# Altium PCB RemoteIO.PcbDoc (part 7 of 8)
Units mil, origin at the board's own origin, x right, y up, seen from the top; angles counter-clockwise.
Board outline 7874.02 x 2362.2 mil, 6 copper layers (Top Layer, GND1, Layer 2, PWR, GND2, Bottom Layer), stack 60.956 mil thick; 655 components, 447 nets, 2607 pads, 1444 vias.
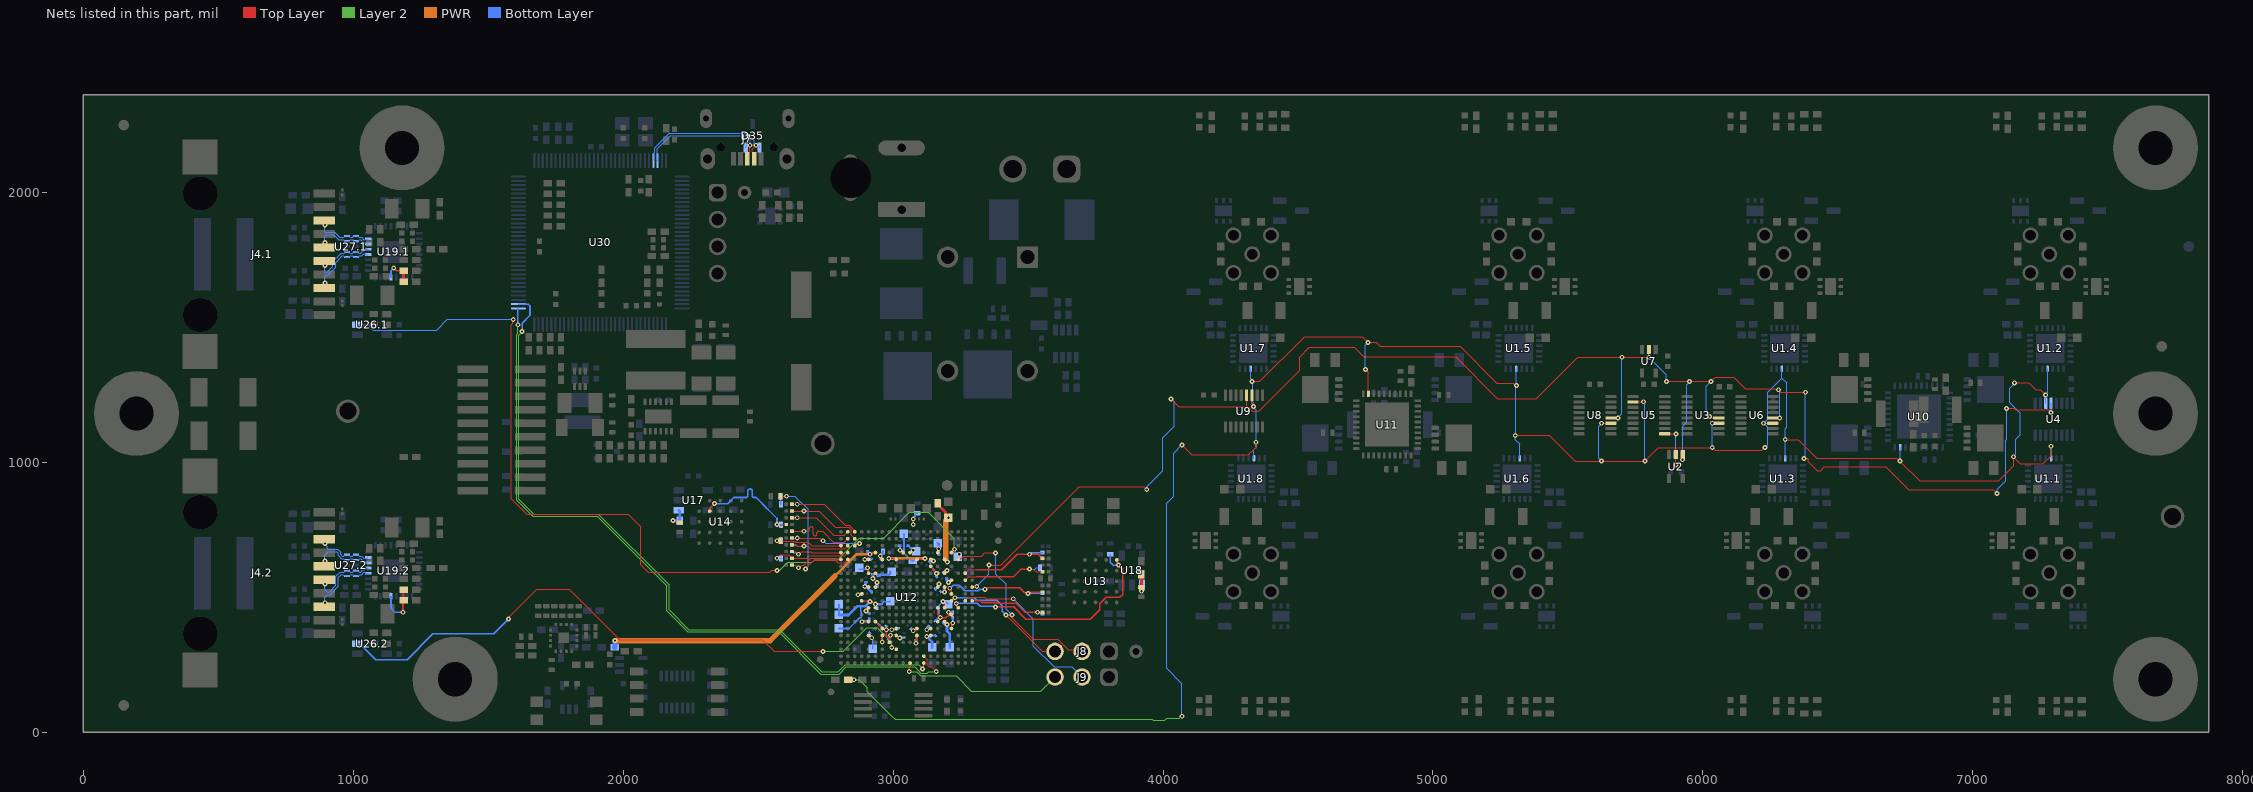
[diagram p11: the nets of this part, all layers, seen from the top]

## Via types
v1: diameter 18, hole 8, Top Layer to Bottom Layer, tented both sides, 1277 vias
v2: diameter 19.68, hole 7.87, Top Layer to Bottom Layer, tented both sides, 133 vias
v3: diameter 19.68, hole 7.87, Top Layer to Bottom Layer, 34 vias

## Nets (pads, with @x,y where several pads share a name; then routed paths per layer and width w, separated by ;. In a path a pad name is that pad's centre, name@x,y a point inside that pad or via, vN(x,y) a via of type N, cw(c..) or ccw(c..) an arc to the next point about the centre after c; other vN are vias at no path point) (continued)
OSPI0_D5: R49.1 R58.1 U12.K1 | length 299.4
  Top Layer w4: v1(3535,445) R58.1@3553.98,445
  Top Layer w6: U12.K1@3293.11,487.2 3322.8,487.2 3329,481 3386.63,481 3388.63,479 3455,479 3489,445 v1(3535,445)
  Bottom Layer w6: v1(3535,445) 3537.3,442.7 3549.89,442.7 3552.59,440 R49.1@3553.98,440
OSPI0_D6: R50.1 R59.1 U12.P2 | length 374.2
  Top Layer w4: U12.P2@3267.52,589.57 3282.28,604.33 3286.42,604.33 3287.98,602.77 3310,602.77
  Top Layer w5: R59.1@3553.19,645 R59.1@3553.98,645
  Top Layer w6: 3310,602.77 3402.77,602.77 3460,660 v1(3505,660) 3538.19,660 R59.1@3553.19,645
  Bottom Layer w5: v1(3505,660) 3508.52,660 3513.52,665
  Bottom Layer w6: 3513.52,665 R50.1@3553.98,665
OSPI0_D7: R51.1 R60.1 U12.L4 | length 454.5
  Top Layer w5: v1(3340,530) 3342.93,530 3349.43,536.5 3468.5,536.5 3488.33,516.67 3498.33,516.67 v1(3500,515) 3503.52,515 3508.52,520 R60.1@3553.98,520 R60.1@3558.34,520
  Top Layer w6: v1(3210.21,534.14) 3210.21,530.89 3214.85,526.26 3214.85,514.28 U12.L4@3216.34,512.8
  Bottom Layer w5: v1(3210.21,534.14) 3211.83,534.14 3222.69,545 3245,545 3265,525 3315.22,525 3320.22,530 v1(3340,530) ; v1(3500,515) R51.1@3553.98,515
OSPI0_DQS: R52.1 R61.2 U12.N2 | length 349.7
  Top Layer w4: U12.N2@3267.52,563.98 3279.91,576.37 3310,576.37 ; v1(3505,605) 3520,605 3530,595 R52.1@3553.98,595
  Top Layer w6: 3310,576.37 3446.37,576.37 3475,605 v1(3505,605)
  Bottom Layer w4: v1(3505,605) 3525,605 3530,610 R61.2@3545,610
OSPI0_ECC_FAIL: R42.1 U12.J3 U13.A5 | length 910.5
  Top Layer w5: v1(3380,465) 3446.31,465 3491.31,420 3730,420 3765,455 3765,475.83 3789.17,500 3840,500 3850,510 3850,605 v1(3835,620) 3830.42,624.58 3830.42,637.06 U13.A5@3828.74,638.74
  Top Layer w6: v1(3234,477.75) 3236.29,475.46 3236.29,469.36 3241.93,463.72 U12.J3@3241.93,461.61
  Bottom Layer w5: v1(3234,477.75) 3312.25,477.75 3322.51,467.49 3377.51,467.49 v1(3380,465) ; R42.1@3805,660 3805,630 3815,620 v1(3835,620)
OSPI0_RST: R97.1 R98.1 U18.1 | length 83.7
  Top Layer w10: v1(3920,523.16) R98.1@3920,537.72 R97.1@3920,585
  Bottom Layer w10: v1@3920,525 3921.2,526.2 3921.2,544.67 U18.1@3922.4,545.87
OSPI1_C\S\: R64.1 R87.1 R88.1 U12.T19 | length 583.5
  Top Layer w4: R87.1@2582.72,875 v1(2605,875) ; v1(2675,605) 2675,607.66 2705.29,637.95 2785.41,637.95 2795,628.36 2820.09,628.36 U12.T19@2832.48,640.75
  Bottom Layer w4: R88.1@2582.72,875 v1(2605,875) 2636.21,875 2651.21,860 2685,826.21 2685,825 2685.77,824.23 2685.77,615.77 v1(2675,605)
  Bottom Layer w6: R88.1@2582.72,875 2583.86,873.86 2583.86,846.14 R64.1@2585,845
OSPI1_CLK: R84.2 R86.1 U14.B2 | length 431.1
  Top Layer w4: v1(2570,770) R86.1@2603.98,770
  Top Layer w6: U14.B2@2320.63,819.37 2320.63,829.89 v1(2338.26,847.52)
  Bottom Layer w4: v1(2570,770) R84.2@2585,770
  Bottom Layer w6: v1(2338.26,847.52) 2387.52,847.52 2410,870 2451.33,870 2454.33,870 ccw(c2454.33,878) 2462.33,878 2462.33,893.72 cw(c2470.33,893.72) 2478.33,893.72 2478.33,878 ccw(c2486.33,878) 2486.33,870 2492.66,870 2500.18,862.48 2530.5,832.16 2530.5,830.1 2534.6,826 2536.66,826 2570,792.66 v1(2570,770)
OSPI1_D0: R65.1 R75.1 U12.V19 | length 264
  Top Layer w4: R75.1@2626.02,695 2639.11,695 2644.11,690 v1(2670,690) 2685,690 2695.46,679.54 2820.09,679.54 U12.V19@2832.48,691.93
  Bottom Layer w4: R65.1@2626.02,695 2639.11,695 2644.11,690 v1(2670,690)
OSPI1_D1: R66.1 R76.1 U12.Y18 | length 296.2
  Top Layer w4: R76.1@2626.02,845 v1(2645,845) 2745,845 2822,768 2838.31,768 2853.1,753.21 2855.4,750.91 2855.4,750.34 2856.2,749.54 2856.2,744.98 U12.Y18@2858.07,743.11
  Bottom Layer w4: R66.1@2626.02,845 v1(2645,845)
OSPI1_D2: R67.1 R77.1 U12.W18 | length 329.8
  Top Layer w4: R77.1@2626.02,820 v1(2670,820) 2726.31,820 2786.31,760 2835,760 2845.6,749.4 2845.6,729.99 U12.W18@2858.07,717.52
  Bottom Layer w4: R67.1@2626.02,820 v1(2670,820)
OSPI1_D3: R68.1 R78.1 U12.Y19 | length 257.8
  Top Layer w4: R78.1@2626.02,795 v1(2645,795) 2715,795 2780,730 2819.37,730 U12.Y19@2832.48,743.11
  Bottom Layer w4: R68.1@2626.02,795 v1(2645,795)
OSPI1_D4: R69.1 R79.1 U12.W19 | length 322.2
  Top Layer w4: R79.1@2626.02,745 v1(2670,745) 2681,745 2683,745 ccw(c2683,752) 2690,752 2690,755 cw(c2697,755) 2704,755 2704,735 ccw(c2711,735) 2718,735 2718,738 cw(c2725,738) 2725,745 2738.69,745 2778.69,705 2819.96,705 U12.W19@2832.48,717.52
  Bottom Layer w4: R69.1@2626.02,745 v1(2670,745)
OSPI1_D5: R70.1 R80.1 U12.U20 | length 218.8
  Top Layer w4: R80.1@2626.02,670 2639.11,670 2649.11,660 v1(2650,660) 2651.21,660 2661.21,670 2695,670 2698.66,666.34 U12.U20@2806.89,666.34
  Bottom Layer w4: R70.1@2626.02,670 2630.32,665.7 2640.51,665.7 2646.21,660 v1(2650,660)
OSPI1_D6: R71.1 R81.1 U12.T20 | length 230.2
  Top Layer w4: R81.1@2626.02,620 2639.11,620 2649.11,610 v1(2650,610) 2651.21,610 2661.21,620 2670,620 2695.95,645.95 2789.8,645.95 2795,640.75 U12.T20@2806.89,640.75
  Bottom Layer w4: R71.1@2626.02,620 2639.11,620 2649.11,610 v1(2650,610)
OSPI1_D7: R72.1 R82.1 U12.V18 | length 296.5
  Top Layer w4: R82.1@2626.02,720 v1(2645,720) 2728.79,720 2738.79,710 v1(2740,710)
  Top Layer w5: U12.V18@2858.07,691.93 2860.45,691.93 2866.03,697.51 2872.51,697.51 v1(2875,700)
  Bottom Layer w4: R72.1@2626.02,720 v1(2645,720) ; v1(2740,710) 2741.21,710 2751.21,700 v1(2875,700)
OSPI1_DQS: R74.1 R83.2 U12.U19 | length 296.1
  Top Layer w4: v1(2570,645) 2582.3,657.3 2613.55,657.3 2620.94,649.91 2620.94,649.3 R74.1@2625.24,645 ; R74.1@2626.02,645 2680,645 2688.95,653.95 2820.09,653.95 U12.U19@2832.48,666.34
  Bottom Layer w4: v1(2570,645) R83.2@2585,645
OSPI1_ECC_FAIL: R63.1 R73.1 U12.V20 | length 257.1
  Top Layer w4: v1(2570,710) R73.1@2582.72,710 ; R73.1@2585,710 2587.5,707.5 2635.39,707.5 2637.89,705 2685,705 2698.07,691.93 U12.V20@2806.89,691.93
  Bottom Layer w4: v1(2570,710) R63.1@2585,710
OSPI1_RST: R95.1 R99.1 U17.1 | length 94.3
  Top Layer w4: v1(2185,785) 2192.28,777.72 R99.1@2210,777.72
  Bottom Layer w5: v1(2185,785) 2208.62,785 R95.1@2210,783.62
  Bottom Layer w10: U17.1@2205.87,822.6 2210,818.46 R95.1@2210,783.62
RD.1_N: J4.1.8 U19.1.4 U27.1.1 U27.1.10 | length 262.8
  Top Layer w4.32: J4.1.8@892.91,1646.65 892.91,1662.91 v1(895,1665)
  Bottom Layer w4.32: v1(895,1665) 895,1690.31 897.53,1692.84 904.97,1692.84 934.41,1722.28 934.41,1740.7 959.52,1765.81 965.63,1765.81 968.16,1763.28 968.16,1762.41 969.94,1760.63 U27.1.1@977.13,1760.63 984.31,1760.63 986.09,1762.41 986.09,1763.28 988.62,1765.81 998.51,1765.81 1001.04,1763.28 1001.04,1762.41 1002.81,1760.63 U27.1.10@1010,1760.63 1017.19,1760.63 1018.96,1762.41 1018.96,1763.28 1021.49,1765.81 1031.46,1765.81 1039.75,1774.1 1044.68,1774.1 1048.62,1770.16 U19.1.4@1055.51,1770.16
RD.1_P: J4.1.6 U19.1.5 U27.1.2 U27.1.9 | length 262.1
  Top Layer w4.32: J4.1.6@892.91,1746.65 895,1744.57 v1(895,1730)
  Bottom Layer w4.32: v1(895,1730) 895,1704.69 897.53,1702.16 901.11,1702.16 925.09,1726.14 925.09,1744.56 955.66,1775.13 965.63,1775.13 968.16,1777.66 968.16,1778.54 969.94,1780.32 U27.1.2@977.13,1780.32 984.31,1780.32 986.09,1778.54 986.09,1777.66 988.62,1775.13 998.51,1775.13 1001.04,1777.66 1001.04,1778.54 1002.81,1780.32 U27.1.9@1010,1780.32 1017.19,1780.32 1018.96,1778.54 1018.96,1777.66 1021.49,1775.13 1027.6,1775.13 1035.89,1783.42 1042.2,1783.42 1048.62,1789.84 U19.1.5@1055.51,1789.84
RD.2_N: J4.2.8 U19.2.4 U27.2.1 U27.2.10 | length 280.3
  Top Layer w4.32: J4.2.8@892.91,465.55 897.36,470 J4.2.8@920,470
  Bottom Layer w4.32: v1(895,480) 895,500.68 905,510.68 914.54,510.68 945,541.14 945,574.71 955,584.71 959.52,584.71 965.63,584.71 968.16,582.18 968.16,581.3 969.94,579.53 U27.2.1@977.13,579.53 984.31,579.53 986.09,581.3 986.09,582.18 988.62,584.71 998.51,584.71 1001.04,582.18 1001.04,581.3 1002.81,579.53 U27.2.10@1010,579.53 1017.19,579.53 1018.96,581.3 1018.96,582.18 1021.49,584.71 1031.46,584.71 1039.75,593 1044.68,593 1048.62,589.06 U19.2.4@1055.51,589.06
RD.2_P: J4.2.6 U19.2.5 U27.2.2 U27.2.9 | length 268.1
  Top Layer w4.32: J4.2.6@892.91,565.55 895,563.46 v1(895,550)
  Bottom Layer w4.32: v1(895,550) 895,530 905,520 910.68,520 935.68,545 935.68,578.57 951.14,594.03 955.66,594.03 965.63,594.03 968.16,596.56 968.16,597.44 969.94,599.21 U27.2.2@977.13,599.21 984.31,599.21 986.09,597.44 986.09,596.56 988.62,594.03 998.51,594.03 1001.04,596.56 1001.04,597.44 1002.81,599.21 U27.2.9@1010,599.21 1017.19,599.21 1018.96,597.44 1018.96,596.56 1021.49,594.03 1027.6,594.03 1035.89,602.32 1042.2,602.32 1048.62,608.74 U19.2.5@1055.51,608.74
RESET_PHY0: U12.U4 U26.1.2 | length 3294
  Top Layer w4: v1(1593,1530) 1591,1528 1591,1515 1586,1510 1586,865.31 1643.31,808 2018.12,808 2065,761.12 2065,620.51 2092.51,593 2543,593 2550,600 v1(2570,600)
  Top Layer w6: U12.U4@3216.34,666.34 3216.34,666.95 3227.5,678.11 v1(3227.5,678.72)
  Layer 2 w4: v1(2570,600) 2580,600 2610,630 2700,630 2710,640 2794.49,640 2874.49,720 2965,720 3060,815 3130,815 3227.5,717.5 v1(3227.5,678.72)
  Bottom Layer w4: U26.1.2@1015.87,1510 1055,1510 1074.59,1490.41 1308.67,1490.41 1348.27,1530 v1(1593,1530)
RESET_PHY1: U12.C12 U26.2.2 | length 2308.5
  Top Layer w4: v1(1575,420) 1574.16,420.84 1574.16,424.16 1680,530 1801.06,530 1826.06,505 1826.21,505 1987.21,344 2515.49,344 2559.49,300 v1(2740,300) ; v1(2995.01,314.28) 2998.8,314.28 3003.13,309.94 3009.74,309.94 U12.C12@3011.61,308.07
  Layer 2 w4: v1(2740,300) 2785,300 2815.34,300 2902.34,387 2942.49,387 2944.99,384.5 2946.01,384.5 2975.5,355.01 2975.5,353.99 2983.99,345.5 2985.01,345.5 2995.01,335.5 v1(2995.01,314.28)
  Bottom Layer w5: U26.2.2@1015.87,328.9 1023.74,328.9 1082.64,270 1200,270 1295,365 1520,365 v1(1575,420)
SCLK: R40.2 U1.1.22 U1.2.22 U1.3.22 U1.4.22 U1.5.22 U1.6.22 U1.7.22 U1.8.22 U3.11 U4.11 U5.2 U6.11 U8.11 U9.11 U10.9 U11.9 | length 8786.6
  Top Layer w4: R40.2@2833.62,195 v1(2855,195) ; v1(4070,1065) 4107,1028 4316.69,1028 4345,1056.31 v1(4345,1075) ; U9.11@4329.53,1249.06 4329.53,1216.79 4335.53,1210.79 v1(4335.53,1207) ; v1(4330,1300) 4358.79,1300 4524.79,1466 4739,1466 v1(4760,1445) 4790,1445 4804,1431 5100.31,1431 5237.31,1294 5297.79,1294 5306.79,1285 v1(5310,1285) ; v1(4750,1345) 4761.1,1333.9 U11.9@4761.1,1254.17 ; v1(5305,1100) 5431.31,1100 5526.31,1005 v1(5625,1005) v1(5785,1005) 5835,1055 v1(6035,1055) 6036.21,1055 6046.21,1045 6218.79,1045 6228.79,1055 v1(6230,1055) ; v1(5625,1145) 5625.47,1145.47 U8.11@5659.06,1145.47 ; U5.2@5740.94,1224.21 5741.34,1224.61 5779.61,1224.61 v1(5780,1225) ; v1(6035,1145) 6058.58,1145 U3.11@6059.06,1145.47 ; v1(6225,1145) 6225.24,1145.24 6258.82,1145.24 U6.11@6259.06,1145.47 ; v1(6305,1085) 6352.47,1085 6421.47,1016 6719,1016 v1(6730,1005) 6803,932 7095.79,932 7151.21,987.43 v1@7151.21,1018.79 ; v1(7151.21,1021.21) v1@7151.21,1018.79 ; v1@7160,1295 7207.37,1295 7232.37,1270 7250,1270 v1(7270,1250) ; v1(7290,1060) 7290,1025 7260,995 7175,995 v1@7151.21,1018.79
  Layer 2 w4: v1(2855,195) 2875,195 2905,165 2905,151.31 2992.31,64 3008.31,48 3960.79,48 3963.79,45 4006.21,45 4014.21,53 4060.66,53 4067.66,60 v1(4070,60)
  Bottom Layer w4: v1(4070,60) 4070,179.74 4013,236.74 4013,849.06 4039,875.06 4039,1034 v1(4070,1065) ; U1.7.22@4324.33,1346.91 4324.33,1309.46 4330,1303.79 v1(4330,1300) 4331.77,1298.23 4331.77,1224 4333.77,1222 4333.77,1205 4345,1193.77 v1(4345,1075) 4345,1055 4337.09,1047.09 U1.8.22@4337.09,1015.3 ; v1(4750,1345) 4750,1433.79 4760,1443.79 v1(4760,1445) ; U1.5.22@5308.58,1346.91 5309.29,1346.2 5309.29,1285.71 v1(5310,1285) 5307.5,1282.5 5307.5,1102.5 v1(5305,1100) 5305,1085 5321.34,1068.66 U1.6.22@5321.34,1015.3 ; v1(5625,1005) 5615,1015 5615,1135 v1(5625,1145) ; v1(5780,1225) 5780,1221.21 5785,1216.21 v1(5785,1005) ; v1(6035,1055) v1(6035,1145) ; v1(6230,1055) 6230,1056.21 6240,1066.21 6240,1130 v1(6225,1145) 6240,1160 6240,1260 6292.83,1312.83 ; U1.4.22@6292.83,1346.91 6292.83,1312.83 ; U1.3.22@6305.59,1015.3 6305.3,1015.59 6305.3,1084.7 v1(6305,1085) 6305,1125 6310,1130 6310,1295.67 6292.83,1312.83 ; v1(6730,1005) 6730.55,1005.55 6730.55,1055.28 U10.9@6731.1,1055.83 ; v1@7151.21,1021.54 7160,1030.33 7160,1086.21 7176,1102.21 7176,1182.69 7137,1221.69 7137,1275.79 7155,1293.79 v1(7155,1295) ; U4.11@7270.47,1219.06 7270.24,1219.29 7270.24,1249.76 v1(7270,1250) 7270,1253.79 7277.09,1260.87 U1.2.22@7277.09,1346.91 ; U1.1.22@7289.84,1015.3 7289.92,1015.37 7289.92,1059.92 v1(7290,1060)
SR_C\S\: U2.1 U3.12 U4.12 U6.12 U7.2 U8.12 U9.12 U12.M1 | length 6454.5
  Top Layer w4: U12.M1@3293.11,538.39 3294.42,539.69 3308.69,539.69 v1(3310,541) ; v1(3355,620) 3398.94,620 3688.94,910 3930,910 v1(3940,900) ; v1(4030,1235) 4059,1206 4309.84,1206 ; U9.12@4309.84,1249.06 4309.84,1206 ; U8.12@5659.06,1165.16 5659.13,1165.08 5684.92,1165.08 v1(5685,1165) ; U7.2@5800,1419.29 v1(5800,1390) v1(5700,1390) 5536.47,1390 5382.47,1236 5238.75,1236 5083.75,1391 4743.75,1391 4708.75,1426 4541.36,1426 4506,1390.64 4506,1341 4355,1190 4331.31,1190 4315.31,1206 4309.84,1206 ; v1(5865,1300) v1(5950,1300) v1(6030,1300) 6045,1315 6115,1315 6156.21,1273.79 6266.21,1273.79 6268.81,1271.19 6277.97,1271.19 v1(6280,1269.16) 6289.16,1260 v1(6380,1260) ; v1(5925,1010) 5925.59,1010.59 U2.1@5925.59,1029.29 ; v1(6025,1170) 6028.79,1170 6033.63,1165.16 U3.12@6059.06,1165.16 ; U6.12@6259.06,1165.16 6259.13,1165.08 6285,1165.08 v1(6285.08,1165) ; v1(6375,1015) 6388.53,1015 6390.88,1012.66 6390.88,1002.91 6423.79,970 6436.21,970 6450.21,984 6678.37,984 6763.37,899 7076,899 v1(7090,885) ; v1(7125,1200) 7153,1200 7157.79,1195.21 7282.31,1195.21 7290,1187.53 v1(7290,1185)
  Bottom Layer w4: v1(3310,541) 3355,586 v1(3355,620) ; v1(3940,900) 3941.61,901.61 3941.61,911.61 3999,969 3999,1091.63 4040.86,1133.49 4040.86,1224.14 v1(4030,1235) ; v1(5685,1165) 5700,1180 v1(5700,1390) ; v1(5800,1390) 5865,1325 v1(5865,1300) ; v1(5925,1010) 5925,1133.79 5940,1148.79 5940,1288.79 5950,1298.79 v1(5950,1300) ; v1(6025,1170) 6025,1172.34 6018.67,1178.67 6018.67,1189.27 6013,1194.95 6013,1283 v1(6030,1300) ; v1(6280,1269.16) 6280,1265.37 6285.08,1260.3 v1(6285.08,1165) ; v1(6375,1015) 6380,1020 v1(6380,1260) ; v1(7090,885) 7090,900 7122,932 7122,1082.15 7125,1085.15 v1(7125,1200) ; v1(7290,1185) 7290.16,1185.16 U4.12@7290.16,1219.06
SR_OUT: U2.2 U5.9 | length 195.7
  Top Layer w4: U5.9@5859.06,1106.1 5859.61,1105.55 5899.45,1105.55 v1(5900,1105) ; v1(5900,990) U2.2@5900,1029.29
  Bottom Layer w4: v1(5900,990) v1(5900,1105)
Strap3.1: R168.1.1 R178.1.2 U19.1.29 | length 119.1
  Top Layer w6: v1(1150,1720) 1151.63,1720 1161.63,1710 R168.1.1@1186.38,1710
  Top Layer w10: R178.1.2@1186.38,1670 R168.1.1@1186.38,1710
  Bottom Layer w6: U19.1.29@1140.16,1685.51 1140.16,1710.16 v1(1150,1720)
Strap3.2: R168.2.1 R178.2.2 U19.2.29 | length 180
  Top Layer w8: v1(1185,445) 1185,487.52 R178.2.2@1186.38,488.9 R168.2.1@1186.38,528.9
  Bottom Layer w6: U19.2.29@1140.16,504.41 1140.16,459.84 1155,445 v1(1185,445)
TD.1_N: J4.1.5 U19.1.6 U27.1.4 U27.1.7 | length 255.5
  Top Layer w4.32: v1(895,1815) 892.91,1812.91 J4.1.5@892.91,1796.65 J4.1.5@917.91,1796.65
  Bottom Layer w4.32: v1(895,1815) 895,1840.31 897.53,1842.84 927.88,1842.84 945.85,1824.87 965.63,1824.87 968.16,1822.34 968.16,1821.46 969.94,1819.69 U27.1.4@977.13,1819.69 984.31,1819.69 986.09,1821.46 986.09,1822.34 988.62,1824.87 998.51,1824.87 1001.04,1822.34 1001.04,1821.46 1002.81,1819.69 U27.1.7@1010,1819.69 1017.19,1819.69 1018.96,1821.46 1018.96,1822.34 1021.49,1824.87 1027.6,1824.87 1035.89,1816.58 1041.57,1816.58 1048.62,1809.53 U19.1.6@1055.51,1809.53
TD.1_P: J4.1.3 U19.1.7 U27.1.5 U27.1.6 | length 252.3
  Top Layer w4.32: v1(895,1880) 895,1894.57 J4.1.3@892.91,1896.65 J4.1.3@917.91,1896.65
  Bottom Layer w4.32: v1(895,1880) 895,1854.69 897.53,1852.16 931.74,1852.16 949.71,1834.19 965.63,1834.19 968.16,1836.72 968.16,1837.59 969.94,1839.37 U27.1.5@977.13,1839.37 984.31,1839.37 986.09,1837.59 986.09,1836.72 988.62,1834.19 998.51,1834.19 1001.04,1836.72 1001.04,1837.59 1002.81,1839.37 U27.1.6@1010,1839.37 1017.19,1839.37 1018.96,1837.59 1018.96,1836.72 1021.49,1834.19 1031.46,1834.19 1039.75,1825.9 1043.33,1825.9 1043.88,1826.45 1052.75,1826.45 U19.1.7@1055.51,1829.21
TD.2_N: J4.2.5 U19.2.6 U27.2.4 U27.2.7 | length 238.3
  Top Layer w4.32: J4.2.5@892.91,615.55 895,617.64 v1(895,635)
  Bottom Layer w4.32: v1(895,635) 895,655.68 907.73,668.41 938.41,668.41 943.98,662.84 943.98,655.45 955.66,643.76 965.63,643.76 968.16,641.23 968.16,640.36 969.94,638.58 U27.2.4@977.13,638.58 984.31,638.58 986.09,640.36 986.09,641.23 988.62,643.76 998.51,643.76 1001.04,641.23 1001.04,640.36 1002.81,638.58 U27.2.7@1010,638.58 1017.19,638.58 1018.96,640.36 1018.96,641.23 1021.49,643.76 1027.6,643.76 1035.89,635.48 1041.57,635.48 1048.62,628.43 U19.2.6@1055.51,628.43
TD.2_P: J4.2.3 U19.2.7 U27.2.5 U27.2.6 | length 221.7
  Top Layer w4.32: J4.2.3@892.91,715.55 895,713.46 v1(895,700)
  Bottom Layer w4.32: v1(895,700) 895,696.3 903.73,687.57 903.73,681.73 907.73,677.73 942.27,677.73 953.3,666.7 953.3,659.31 959.52,653.09 965.63,653.09 968.16,655.62 968.16,656.49 969.94,658.27 U27.2.5@977.13,658.27 984.31,658.27 986.09,656.49 986.09,655.62 988.62,653.09 998.51,653.09 1001.04,655.62 1001.04,656.49 1002.81,658.27 U27.2.6@1010,658.27 1017.19,658.27 1018.96,656.49 1018.96,655.62 1021.49,653.09 1031.46,653.09 1039.75,644.8 1043.33,644.8 1043.88,645.35 1052.75,645.35 U19.2.7@1055.51,648.11
UART0_RX: U12.A8 U30.34 | length 2634
  Top Layer w4: v1(3109.42,235) 3109.42,238.79 3113.98,243.34 U12.A8@3113.98,256.89
  Layer 2 w4: v1@1625,1482.66 1613,1470.66 1613,863.31 1668.31,808 1908.31,808 2170,546.31 2170,453.43 2243.43,380 2579.75,380 2735.75,224 2797.13,224 2823.13,250 3094.42,250 v1(3109.42,235)
  Bottom Layer w6: U30.34@1611.85,1586.65 1612.21,1586.3 1648.7,1586.3 1655,1580 1655,1545 1626,1516 1626,1486 v1(1625,1485)
UART0_TX: U12.B8 U30.33 | length 2693.8
  Top Layer w4: U12.B8@3113.98,282.48 3127.18,269.28 3127.18,250.23 3135,242.41 3142.59,242.41 v1(3160,225)
  Layer 2 w4: v1(1610,1510) 1610,1478.97 1605,1473.97 1605,860 1665,800 1905,800 2162,543 2162,450.12 2240.12,372 2576.43,372 2732.43,216 2800.45,216 2826.95,242.5 3080.71,242.5 3091.31,231.89 3103.21,220 3127.21,220 3132.21,225 v1(3160,225)
  Bottom Layer w6: v1(1610,1510) 1610,1570.04 1610.87,1570.91 U30.33@1611.85,1570.91
UART1_RX: J8.2 U12.T3 | length 725.1
  Top Layer w4: U12.T3@3241.93,640.75 3243.8,642.62 3251.87,642.62 3262.39,653.14 3328.14,653.14 3340,665 v1(3380,665) ; v1(3440,435) 3441.26,433.74 3441.26,423.05 3519.31,345 3610,345 3648.86,306.14 3693.86,306.14 J8.2@3700,300
  Bottom Layer w4: v1(3380,665) 3380,586.62 3418.66,547.96 3418.66,456.34 v1(3440,435)
UART1_TX: J8.3 U12.K4 | length 485
  Top Layer w4: v1(3418,435) 3553,300 J8.3@3600,300
  Top Layer w6: U12.K4@3216.34,487.2 3217.25,487.2 3228.89,498.84 v1(3229.8,498.84) 3229.8,499.8 v1@3230,500
  Bottom Layer w5: v1(3229.8,498.84) 3301.16,498.84 3310,490 3385,490 3405.01,469.99 3405.01,447.99 v1(3418,435)
UART2.RX: J9.2 U12.K2 | length 618.6
  Top Layer w4: U12.K2@3267.52,487.2 3280.31,500 3340,500 3345,495 v1(3445,495)
  Bottom Layer w4: v1(3445,495) 3520,420 3520,320 3596.52,243.48 3661.52,243.48 J9.2@3700,205
UART2.TX: J9.3 U12.A10 | length 624.4
  Top Layer w4: v1(3060,225) 3060,241.46 3062.54,244 3062.54,256.64 U12.A10@3062.8,256.89
  Layer 2 w4: v1(3060,225) 3086.89,225 3101.89,210 3233.43,210 3290.43,153 3548,153 J9.3@3600,205
USB_N: D35.1 J7.2 U30.93 | length 551
  Top Layer w4.32: J7.2@2485.59,2125 2485.59,2141.73 2477.46,2149.87 2477.46,2160.03 2492,2174.57 v1(2492,2175)
  Bottom Layer w4.32: U30.93@2111.85,2118.15 2111.85,2142.73 2117.63,2148.51 2117.63,2165.81 2171.14,2219.32 2458.86,2219.32 2486.24,2191.94 2486.24,2178.17 2489.41,2175 v1(2492,2175) 2499.88,2175 2505.59,2169.29 D35.1@2505.59,2166.69
USB_P: D35.2 J7.3 U30.94 | length 507.9
  Top Layer w4.32: J7.3@2460,2125 2460,2141.73 2468.14,2149.87 2468.14,2173.14 v1(2470,2175)
  Bottom Layer w4.32: U30.94@2127.6,2118.15 2126.95,2118.8 2126.95,2161.95 2175,2210 2455,2210 2470,2195 v1(2470,2175) 2460.12,2175 2454.41,2169.29 D35.2@2454.41,2166.69
Vcore: C44.2 C45.2 C46.2 C47.2 C48.2 C49.2 C50.2 C51.2 C52.2 C53.2 C54.2 C55.2 C56.2 C57.2 C58.2 C59.2 C60.2 C61.2 C62.2 C63.2 C64.2 R109.1 U12.D13 U12.F7 U12.F9 U12.F12 U12.F14 U12.G6 U12.G15 U12.H4 U12.J6 U12.J15 U12.K17 U12.M6 U12.M15 U12.P6 U12.P15 U12.R7 | length 1155.1
  Top Layer w6: U12.K17@2883.66,487.2 2884.76,486.1 2913.9,486.1 v1(2915,485) ; v1(2925,570) 2927.3,572.3 2927.3,579.92 2934.84,587.46 U12.P15@2934.84,589.57 U12.P15@2934.49,589.57 ; U12.G15@2934.84,410.43 U12.F14@2960.43,384.84 2961.92,383.35 v1@2968.4,383.35 ; U12.M15@2934.84,538.39 2936.33,539.87 2936.33,548.08 2940,551.75 v1(2940,555) ; v1(2975,380) 2975,360.51 2985.51,350 U12.D13@2985.51,334.17 ; U12.D13@2986.02,333.66 2986.02,352.78 2990,356.75 v1(2990,360) ; v1(2995,380) 2998.25,380 3001.6,383.35 3010.13,383.35 U12.F12@3011.61,384.84 ; v1@3070,380 3073.35,383.35 3086.9,383.35 U12.F9@3088.39,384.84 ; U12.R7@3139.57,615.16 3139.57,613.05 3161.45,591.17 v1(3161.45,588.99) ; U12.G6@3165.16,410.43 3165.16,412.54 3175,422.38 v1(3175,425) ; U12.J6@3165.16,461.61 3165.16,438.09 3175,428.25 v1(3175,425) ; U12.M6@3165.16,538.39 3165.16,540.49 3167.7,543.04 3167.7,547.7 v1(3170,550) ; v1(3205,445) 3208.33,441.67 3209.51,441.67 3215.16,436.02 U12.H4@3216.34,436.02 3214.85,434.54 3207.78,434.54 3203.25,430 3200,430 3195,425 v1(3175,425)
  Bottom Layer w6: C44.2@2799.53,385 2836.92,385 2876.92,425 2880,425 2882.18,427.18 2882.18,447.5 2880,449.68 2880,467.75 2880,470 ; C63.2@2799.53,475 2799.53,435.47 C61.2@2800,435 ; C62.2@2926.13,585.2 2939.8,585.2 C57.2@2943.88,581.12 ; v1(2935,475) 2937.3,472.7 2937.3,465.81 2941.34,461.77 C52.2@2941.34,460 ; C48.2@2948.88,398.88 2965.45,382.3 2972.7,382.3 v1(2975,380) 2975.13,380.13 2975.13,392.62 C60.2@2973.88,393.88 ; 2957.26,475 2965.93,483.67 2988.19,483.67 C46.2@2990,485.47 ; C49.2@2983.88,346.12 2983.88,347.73 2987.7,351.56 2987.7,357.7 v1(2990,360) ; v1(2995,380) 3015,380 C50.2@3020,385 ; C56.2@3066.12,383.88 3066.84,383.88 3075,375.72 v1@3075,375 ; v1(3075,790) 3075,793.25 3081.19,799.44 3081.19,807.41 3086.06,812.28 R109.1@3090,812.28 ; v1(3125,380) 3127.3,382.3 3127.3,388.44 3131.12,392.27 C51.2@3131.12,393.88 ; C59.2@3151.12,601.12 3151.12,600.22 3161.45,589.89 v1(3161.45,588.99) 3159.87,587.41 3159.87,577.38 C64.2@3161.12,576.12 ; C47.2@3156.12,413.88 3164.95,422.7 3172.7,422.7 v1(3175,425) ; C55.2@3156.12,531.12 3155.68,531.57 3155.68,533.18 3170,547.5 v1(3170,550) ; v1(3205,445) C58.2@3221.34,445
  Bottom Layer w10: C61.2@2800,435 2835,435 2867.75,467.75 2880,467.75 2897.75,467.75 v1(2915,485) ; v1(2925,570) C62.2@2925,585 ; v1(2935,475) 2957.26,475 ; v1(2940,555) 2940.67,554.33 2940.67,540.67 C53.2@2941.34,540 ; C57.2@2943.9,581.15 2950.53,581.15 2953.86,584.47 2984.72,584.47 2990,589.75 C45.2@2990,595
  other v1: 3074.92,376.51 3075,770
VDDA18: C75.2 C76.2 C77.2 C78.2 C121.2 C122.2 L2.2 L9.2 U12.T5 U12.U10 U12.U11 U12.U15 | length 1491.1
  Top Layer w6: v1(2915,660) 2918.25,660 2923.1,664.85 2933.35,664.85 U12.U15@2934.84,666.34 ; v1(3025.19,674.76) 3025.43,675 3030,675 3037.2,667.8 U12.U11@3037.2,666.34
  Top Layer w8: U12.U10@3062.8,666.34 3064.36,666.34 3072.78,674.76 v1(3074.81,674.76)
  Top Layer w10: L2.2@3165,848.62 3165,844.68 3194.25,815.43 3194.25,805.75 v1(3205,795) C121.2@3210,790 ; U12.T5@3190.75,640.75 3190.89,640.75 3200.86,630.77 v1(3201,630.77)
  PWR w10: 2785,580 2865,660 v1(2915,660)
  PWR w20: v1(1970,340) 2545,340 2785,580 ; 3195,642.42 3195,785 v1(3205,795)
  Bottom Layer w8: v1@3025,675 3025.1,675.1 3025.1,691.24 C122.2@3025,691.34 ; C77.2@3055,691.34 3056.77,691.34 3065.89,682.22 C75.2@3073.25,682.22 ; C78.2@3190,656.34 3191.77,656.34 3191.91,656.2 3191.91,654.43 3199.08,647.25 3199.08,632.69 v1(3201,630.77)
  Bottom Layer w10: C76.2@2905,671.34 2915,661.38 v1(2915,660)
  Bottom Layer w20: L9.2@1968.62,315 1970,316.38 v1(1970,340)
VDDA33: C100.2 C101.2 C102.2 L3.1 U12.T9 U12.T12 | length 357.1
  Top Layer w6: v1(2983.92,644.55) 3001.92,644.55 3004.23,642.24 3010.13,642.24 U12.T12@3011.61,640.75 ; U12.T9@3088.39,640.75 v1@3110.47,640.75
  PWR w10: v1(2983.92,644.55) 2984.03,644.66 v1@3114.66,644.66
  Bottom Layer w6: C100.2@3040,735.47 3040.69,734.78 3040.69,663.99 3069.68,635 L3.1@3073.62,635 ; L3.1@3075,635 3083.66,643.66 C101.2@3105,643.66
  Bottom Layer w10: v1(2983.92,644.55) 2984.36,644.11 2994.56,644.11 C102.2@2995,643.66 ; C101.2@3105,643.66 3105.56,644.22 3117.18,644.22 v1(3117.74,644.77)
VDDS18: C65.2 C66.2 C67.2 C68.2 C69.2 C70.2 C71.2 C72.2 C73.2 C74.2 U12.E9 U12.E14 U12.F4 U12.G16 U12.L17 U12.N4 U12.T16 U12.U6 | length 358.2
  Top Layer w6: v1(2870,510) 2871.4,511.4 2882.26,511.4 U12.L17@2883.66,512.8 ; v1(2885,410) 2885.22,410.22 2909.04,410.22 U12.G16@2909.25,410.43 ; v1(2960,335) 2960.22,335.22 2960.22,359.04 U12.E14@2960.43,359.25 ; v1(3085,330) 3086.9,331.9 3086.9,357.76 U12.E9@3088.39,359.25 ; U12.U6@3165.16,666.34 3166.65,667.83 3166.65,674.24 3169.27,676.87 v1(3169.27,680.11) ; U12.F4@3216.34,386.95 U12.F4@3216.34,384.84 3217.83,386.33 3217.83,398.89 3220.91,401.97 v1(3220.91,405.22) ; v1(3245,660) v1@3250,660
  Top Layer w10: v1(2895,640) 2895.37,640.37 2908.88,640.37 U12.T16@2909.25,640.75 ; v1(3205,555) 3206.34,555 3215.32,563.98 U12.N4@3216.34,563.98
  Bottom Layer w6: v1(2960,335) 2959.87,335.13 2959.87,362.62 C67.2@2961.12,363.88 ; v1(3085,330) C70.2@3085,341.34 ; v1@3220,405 3221.12,406.12 3221.12,424.78 C69.2@3221.34,425
  Bottom Layer w8: v1(2870,510) 2872.71,510 2875.8,513.09 2886.2,513.09 2886.34,513.23 C74.2@2886.34,515 ; v1(2885,410) 2886.91,411.91 2903.25,411.91 2909.43,418.09 2911.2,418.09 2911.34,418.23 C68.2@2911.34,420
  Bottom Layer w10: v1@2903.26,641.1 C73.2@2918.85,641.1 ; C66.2@3165,700.47 3169.27,696.2 v1(3169.27,680.11) 3169.64,679.75 3169.64,659.02 C72.2@3170,658.66 ; C71.2@3198.66,570 3199.53,569.13 3199.53,562.64 3205,557.16 v1(3205,555)
VDDSHV: C83.2 C84.2 C85.2 C86.2 C87.2 C88.2 C89.2 C90.2 C91.2 C92.2 C93.2 C94.2 C95.2 C96.2 C97.2 C98.2 C99.2 R110.1 U12.E7 U12.E12 U12.E16 U12.G5 U12.J5 U12.J16 U12.M5 U12.M16 U12.P5 U12.P16 U12.T7 U12.T14 | length 697.9
  Top Layer w6: v1(2895,540) 2895.81,539.19 2908.44,539.19 U12.M16@2909.25,538.39 ; v1@2905,605 2905,601.75 2907.76,598.99 2907.76,591.06 U12.P16@2909.25,589.57 ; U12.E16@2909.25,359.25 2910.74,359.25 v1@2919.99,350 ; U12.E12@3011.61,359.25 3013.68,359.25 3022.93,350 v1(3025,350) ; v1(3125,355) 3128.25,355 3131.01,357.76 3138.08,357.76 U12.E7@3139.57,359.25 ; U12.T7@3139.57,640.75 U12.T7@3141.67,640.75 ; v1(3150,635) v1@3147.42,635 ; v1@3189.26,477.49 3189.26,463.1 U12.J5@3190.75,461.61 ; v1(3190,520) 3190.37,520.37 3190.37,538.01 U12.M5@3190.75,538.39 ; U12.P5@3190.75,589.57 3190.75,590.16 3200,599.41 v1(3200,600) ; U12.T7@3141.67,640.75 v1@3147.42,635 ; U12.T7@3141.67,640.75 v1@3147.42,635
  Top Layer w10: v1(2900.3,450.25) 2900.3,451.63 2909.25,460.59 U12.J16@2909.25,461.61 ; v1(2952.37,653.23) 2953.9,651.7 2953.9,648.3 2960.43,641.77 U12.T14@2960.43,640.75 ; U12.G5@3190.75,410.43 3190.75,409.95 3200,400.69 v1(3200,400.21)
  Bottom Layer w6: C84.2@2875,605.47 2875.47,605 v1@2905,605 ; C94.2@2913.88,368.88 2915.13,367.62 2915.13,359.61 v1@2920,354.73 ; C91.2@2924.53,310 v1@2924.53,343.71 ; C88.2@2958.23,638.66 C88.2@2960,638.66 ; v1(3025,350) C97.2@3040,350 ; v1(3125,355) 3143,355 3147,359 3156.5,359 C98.2@3157.75,357.75 ; C83.2@3136.12,631.12 3137.38,629.87 3138.98,629.87 3140.23,631.12 3142.88,631.12 3146.75,635 v1(3150,635) ; C87.2@3170,445 3170,470 v1(3185,485) 3195,485 C86.2@3205,475 ; C89.2@3176.12,521.12 3177.38,519.87 3189.87,519.87 v1(3190,520) ; C90.2@3186.12,593.88 3187.73,593.88 3191.56,597.7 3197.7,597.7 v1(3200,600)
  Bottom Layer w10: v1(2895,540) 2896.53,538.47 2902.25,538.47 2916.3,524.43 2916.3,523.7 C96.2@2920,520 ; v1@2899.09,546.26 2899.09,555.47 C85.2@2900,556.34 ; v1(2900.3,450.25) 2901.13,450.25 C95.2@2911.34,440 ; C88.2@2958.23,638.66 2953.9,642.99 2953.9,651.7 v1(2952.37,653.23) 2953.9,654.76 2953.9,657.68 2962.28,666.06 R110.1@2962.28,670 ; v1(3125,355) 3145,335 C92.2@3145,314.53 ; C99.2@3186.12,406.12 3187.35,406.12 3191.74,401.74 3198.47,401.74 v1(3200,400.21) 3200,375 3210,365 C93.2@3210,314.53
  other v1: 2920.93,350.56 2905,610
pads on no net: FID1.1 FID2.1 FID3.1 FID4.1 FID5.1 FID6.1 H1.1 H3.1 H5.0 H6.0 H7.0 H9.1 H10.0 H11.1 H12.1 H13.0 H14.0 J1.1.5 J1.2.5 J1.3.5 J1.4.5 J1.5.5 J1.6.5 J1.7.5 J1.8.5 J3.2 J3.6 J3.8 J3.9 J3.13 J3.14 J3.15 J3.17 J3.18 J3.19 J4.1.MH1 J4.1.MH2 J4.2.MH1 J4.2.MH2 J7. J7.4 LBL1.0 Q1.9A Q1.9B Q1.9C Q1.9D Q2.9A Q2.9B Q2.9C Q2.9D Q3.9A Q3.9B Q3.9C Q3.9D Q4.9A Q4.9B Q4.9C Q4.9D Q5.9A Q5.9B Q5.9C Q5.9D Q6.9A Q6.9B Q6.9C Q6.9D Q7.9A Q7.9B Q7.9C Q7.9D Q8.9A Q8.9B Q8.9C Q8.9D Q9.9@3292.91,1309.92 Q9.9@3292.91,1380 Q9.9@3350,1309.92 Q9.9@3350,1343.39 Q9.9@3350,1380 Q9.9@3407.09,1309.92 Q9.9@3407.09,1380 Q10.9@2997.91,1304.84 Q10.9@2997.91,1374.92 Q10.9@3055,1304.84 Q10.9@3055,1338.31 Q10.9@3055,1374.92 Q10.9@3112.09,1304.84 Q10.9@3112.09,1374.92 U1.1.5 U1.1.14 U1.1.18 U1.2.5 U1.2.14 U1.2.18 U1.3.5 U1.3.14 U1.3.18 U1.4.5 U1.4.14 U1.4.18 U1.5.5 U1.5.14 U1.5.18 U1.6.5 U1.6.14 U1.6.18 U1.7.5 U1.7.14 U1.7.18 U1.8.5 U1.8.14 U1.8.18 U5.7 U7.1 U9.9 U10.1 U10.22 U10.23 U10.24 U10.25 U10.26 U10.27 U11.1 U11.22 U11.23 U11.24 U11.25 U11.26 U11.27 U12.A2 U12.A4 U12.A5 U12.A6 U12.A7 U12.A9 U12.A14 U12.A17 U12.B3 U12.B4 U12.B5 U12.B6 U12.B7 U12.B9 U12.B14 U12.B16 U12.B19 U12.C14 U12.C19 U12.D10 U12.E19 U12.H1 U12.J2 U12.J19 U12.J20 U12.T2 U12.U17 U12.W4 U12.W5 U12.Y2 U13.A2 U13.A3 U13.B1 U13.B5 U13.C5 U14.A2 U14.B1 U14.B5 U14.C5 U16.1 U19.1.8 U19.1.28 U19.2.8 U19.2.28 U21.1 U22.11 U23.6 U25.3 U26.1.1 U26.2.1 U27.1.3@977.13,1800 U27.1.8@1010,1800 U27.2.3@977.13,618.9 U27.2.8@1010,618.9 U28.7 U29.5 U29.7@2545,1894.57 U29.7@2545,1930 U30.1 U30.2 U30.5 U30.6 U30.11 U30.12 U30.13 U30.14 U30.15 U30.18 U30.19 U30.20 U30.21 U30.22 U30.23 U30.24 U30.25 U30.27 U30.29 U30.30 U30.31 U30.32 U30.40 U30.41 U30.42 U30.43 U30.44 U30.45 U30.46 U30.49 U30.50 U30.53 U30.54 U30.56 U30.57 U30.65 U30.67 U30.71 U30.72 U30.73 U30.74 U30.75 U30.76 U30.77 U30.78 U30.81 U30.82 U30.83 U30.84 U30.85 U30.86 U30.91 U30.92 U30.95 U30.102 U30.103 U30.104 U30.105 U30.106 U30.107 U30.108 U30.109 U30.110 U30.111 U30.112 U30.116 U30.117 U30.118 U30.119 U30.120 U30.121 U30.123 U30.124 U30.125 U30.126 U30.127 U30.128 U31.1.7@7110,692.28 U31.1.7@7110,727.72 U31.2.7@7456.93,1634.49 U31.2.7@7456.93,1669.92 U31.3.7@6125.75,692.28 U31.3.7@6125.75,727.72 U31.4.7@6472.68,1634.49 U31.4.7@6472.68,1669.92 U31.5.7@5488.43,1634.49 U31.5.7@5488.43,1669.92 U31.6.7@5141.5,692.28 U31.6.7@5141.5,727.72 U31.7.7@4504.17,1634.49 U31.7.7@4504.17,1669.92 U31.8.7@4157.24,692.28 U31.8.7@4157.24,727.72 U32.1.7@7372.28,430 U32.1.7@7407.72,430 U32.2.7@7159.21,1932.2 U32.2.7@7194.65,1932.2 U32.3.7@6388.03,430 U32.3.7@6423.46,430 U32.4.7@6174.96,1932.2 U32.4.7@6210.39,1932.2 U32.5.7@5190.71,1932.2 U32.5.7@5226.14,1932.2 U32.6.7@5403.78,430 U32.6.7@5439.21,430 U32.7.7@4206.46,1932.2 U32.7.7@4241.89,1932.2 U32.8.7@4419.53,430 U32.8.7@4454.96,430

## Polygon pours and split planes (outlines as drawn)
GND on Top Layer "TOP_LAYER_GND_P129" (solid, remove dead copper, pour order 129): 2753.69,780 3325.45,780 3325.45,207.5 2753.69,207.5
L+3 on Top Layer "TOP_LAYER_L+3_P320" (solid, remove dead copper, pour order 320): 6475,1140 6575,1140 6575,1040 6475,1040
EARTH on Top Layer "TOP_LAYER_EARTH_P309" (solid, remove dead copper, pour order 309): 500,0 500,2365 0,2365 0,0
GND on Top Layer "TOP_LAYER_GND_P308" (solid, remove dead copper, pour order 308): 560,1330 680,1330 680,1030 560,1030
GND on Top Layer "TOP_LAYER_GND_P307" (solid, remove dead copper, pour order 307): 1380,2020 1380,1453.19 955,1453.19 955,2020
NetC132.1_1 on Top Layer "TOP_LAYER_NETC132.1_1_P306" (solid, remove dead copper, pour order 306): 19 vertices, not listed, extent 1210,1810 1335,1985
NetC129.1_1 on Top Layer "TOP_LAYER_NETC129.1_1_P305" (solid, remove dead copper, pour order 305): 979.68,1535 979.68,1680 1034.68,1680 1064.68,1710 1064.68,1735 1014.68,1735 1014.68,1765 1094.68,1765 1094.68,1535
GND on Top Layer "TOP_LAYER_GND_P304" (solid, remove dead copper, pour order 304): 2615,1715 2730,1715 2730,1530 2615,1530
GND on Top Layer "TOP_LAYER_GND_P301" (solid, remove dead copper, pour order 301): 6640,1410 6640,1350 6580,1350 6580,1410
L+3 on Top Layer "TOP_LAYER_L+3_P163" (solid, remove dead copper, pour order 163): 6105.75,745 6105.75,650 6160.75,595 6305.75,595 6305.75,730 6320.75,745 6360.75,785 6480,785 6565,870 6565,995 6455,995 6335,875 6285.75,875 6285.75,800 6230.75,745
NetQ3_1 on Top Layer "TOP_LAYER_NETQ3_1_P296" (solid, remove dead copper, pour order 296): 6594.92,1130 6645,1130 6645,1095 6585,1095 6585,1120.08
NetQ4_1 on Top Layer "TOP_LAYER_NETQ4_1_P295" (solid, remove dead copper, pour order 295): 6577.96,1296.54 6627.96,1296.54 6627.96,1221.54 6577.96,1221.54
L+4 on Top Layer "TOP_LAYER_L+4_P290" (solid, remove dead copper, pour order 290): 6470,1215 6580,1215 6580,1325 6555,1350 6555,1415 6545,1415 6470,1415
24V on Top Layer "TOP_LAYER_24V_P289" (solid, remove dead copper, pour order 289): 6680.41,1235.12 6680.41,1130.12 6595,1130.12 6595,1235.12
L+5 on Top Layer "TOP_LAYER_L+5_P285" (solid, remove dead copper, pour order 285): 5045,1320 5145,1320 5145,1220 5045,1220
NetQ5_1 on Top Layer "TOP_LAYER_NETQ5_1_P282" (solid, remove dead copper, pour order 282): 4930,1180 4965,1180 4985,1200 5040,1200 5040,1290 4985,1290 4985,1240 4965,1220 4930,1220
24V on Top Layer "TOP_LAYER_24V_P281" (solid, remove dead copper, pour order 281): 2450,1175 2450,1220 2475,1245 2515,1245 2515,1205 2485,1175
GND on Top Layer "TOP_LAYER_GND_P279" (solid, remove dead copper, pour order 279): 4990,949.86 4990,1009.86 5055,1009.86 5055,949.86
L+6 on Top Layer "TOP_LAYER_L+6_P277" (solid, remove dead copper, pour order 277): 5045,1140 5145,1140 5145,950 5085,950 5085,1000 5045,1040
24V on Top Layer "TOP_LAYER_24V_P274" (solid, remove dead copper, pour order 274): 4930,1180 4960,1180 4975,1195 5040,1195 5040,1145 5000,1145 4960,1105 4930,1105
NetQ6_1 on Top Layer "TOP_LAYER_NETQ6_1_P273" (solid, remove dead copper, pour order 273): 4930,1100 4960,1100 5000,1140 5040,1140 5040,1065 4930,1065
24V on Top Layer "TOP_LAYER_24V_P096" (solid, remove dead copper, pour order 96): 4635,1195 4675,1195 4685,1185 4685,1180 4735,1180 4735,1100 4695,1100 4650,1145 4635,1145
L+8 on Top Layer "TOP_LAYER_L+8_P272" (solid, remove dead copper, pour order 272): 4515,1140 4615,1140 4615,1040 4515,1040
NetQ8_1 on Top Layer "TOP_LAYER_NETQ8_1_P099" (solid, remove dead copper, pour order 99): 4730,1100 4695,1100 4650,1145 4615,1145 4615,1065 4730,1065
GND on Top Layer "TOP_LAYER_GND_P266" (solid, remove dead copper, pour order 266): 4680,1410.14 4680,1350.14 4615,1350.14 4615,1410.14
L+7 on Top Layer "TOP_LAYER_L+7_P264" (solid, remove dead copper, pour order 264): 4620,1220 4515,1220 4515,1410 4600,1410 4600,1345 4620,1325
NetQ7_1 on Top Layer "TOP_LAYER_NETQ7_1_P260" (solid, remove dead copper, pour order 260): 4735,1185 4665,1185 4625,1225 4625,1295 4685,1295 4685,1265 4730,1220 4735,1220
GND on Top Layer "TOP_LAYER_GND_P259" (solid, remove dead copper, pour order 259): 2470,1850 2470,1985 2675,1985 2675,1850
NetQ2_1 on Top Layer "TOP_LAYER_NETQ2_1_P257" (solid, remove dead copper, pour order 257): 6955,1295 7000,1295 7000,1260 6940,1260 6940,1280
L+2 on Top Layer "TOP_LAYER_L+2_P255" (solid, remove dead copper, pour order 255): 7015,1600 7115,1600 7300,1600 7300,1505 7265,1470 7230,1470 7115,1355 7115,1220 7015,1220
24V on Top Layer "TOP_LAYER_24V_P249" (solid, remove dead copper, pour order 249): 7005,1250 7005,1145 6919.59,1145 6919.59,1250
GND on Top Layer "TOP_LAYER_GND_P248" (solid, remove dead copper, pour order 248): 6700,1270 6900,1270 6900,1070 6700,1070
GND on Top Layer "TOP_LAYER_GND_P246" (solid, remove dead copper, pour order 246): 7025,1010 7025,950 6965,950 6965,1010
NetQ1_1 on Top Layer "TOP_LAYER_NETQ1_1_P244" (solid, remove dead copper, pour order 244): 6960,1140 7010,1140 7010,1065 6960,1065
L+1 on Top Layer "TOP_LAYER_L+1_P243" (solid, remove dead copper, pour order 243): 7045,950 7035,960 7035,1025 7015,1045 7015,1145 7130,1145 7130,950
NetJ1.8_4 on Top Layer "TOP_LAYER_NETJ1.8_4_P160" (solid, remove dead copper, pour order 160): 4192.24,590 4327.24,590 4327.24,375 4192.24,375
L+8 on Top Layer "TOP_LAYER_L+8_P168" (solid, remove dead copper, pour order 168): 4137.24,745 4137.24,650 4192.24,595 4337.24,595 4337.24,730 4352.24,745 4395,787.76 4395,840 4315,840 4315,797.76 4262.24,745
GND on Top Layer "TOP_LAYER_GND_P192" (solid, remove dead copper, pour order 192): 4332.24,375 4502.24,375 4502.24,585 4332.24,585
NetJ1.8_2 on Top Layer "TOP_LAYER_NETJ1.8_2_P208" (solid, remove dead copper, pour order 208): 4342.24,600 4502.24,600 4502.24,785 4342.24,785
NetU31.8_4 on Top Layer "TOP_LAYER_NETU31.8_4_P232" (solid, remove dead copper, pour order 232): 4077.24,750 4137.24,750 4137.24,665 4077.24,665
GND on Top Layer "TOP_LAYER_GND_P240" (solid, remove dead copper, pour order 240): 4247.24,835 4247.24,765 4187.24,765 4177.24,775 4177.24,825 4187.24,835
NetJ1.7_4 on Top Layer "TOP_LAYER_NETJ1.7_4_P159" (solid, remove dead copper, pour order 159): 4469.17,1772.2 4334.17,1772.2 4334.17,1987.2 4469.17,1987.2
L+7 on Top Layer "TOP_LAYER_L+7_P167" (solid, remove dead copper, pour order 167): 4524.17,1617.2 4524.17,1712.2 4469.17,1767.2 4324.17,1767.2 4324.17,1632.2 4309.17,1617.2 4284.17,1592.2 4284.17,1522.2 4344.17,1522.2 4344.17,1562.2 4399.17,1617.2
GND on Top Layer "TOP_LAYER_GND_P191" (solid, remove dead copper, pour order 191): 4329.17,1987.2 4159.17,1987.2 4159.17,1777.2 4329.17,1777.2
NetJ1.7_2 on Top Layer "TOP_LAYER_NETJ1.7_2_P207" (solid, remove dead copper, pour order 207): 4319.17,1762.2 4159.17,1762.2 4159.17,1577.2 4319.17,1577.2
NetU31.7_4 on Top Layer "TOP_LAYER_NETU31.7_4_P231" (solid, remove dead copper, pour order 231): 4584.17,1612.2 4524.17,1612.2 4524.17,1697.2 4584.17,1697.2
GND on Top Layer "TOP_LAYER_GND_P239" (solid, remove dead copper, pour order 239): 4414.17,1527.2 4414.17,1597.2 4474.17,1597.2 4484.17,1587.2 4484.17,1537.2 4474.17,1527.2
NetJ1.6_4 on Top Layer "TOP_LAYER_NETJ1.6_4_P158" (solid, remove dead copper, pour order 158): 5176.5,590 5311.5,590 5311.5,375 5176.5,375
L+6 on Top Layer "TOP_LAYER_L+6_P166" (solid, remove dead copper, pour order 166): 5121.5,745 5121.5,650 5176.5,595 5321.5,595 5321.5,730 5336.5,745 5361.5,770 5361.5,840 5301.5,840 5301.5,800 5246.5,745
GND on Top Layer "TOP_LAYER_GND_P174" (solid, remove dead copper, pour order 174): 5316.5,375 5486.5,375 5486.5,585 5316.5,585
NetJ1.6_2 on Top Layer "TOP_LAYER_NETJ1.6_2_P198" (solid, remove dead copper, pour order 198): 5326.5,600 5486.5,600 5486.5,785 5326.5,785
NetU31.6_4 on Top Layer "TOP_LAYER_NETU31.6_4_P214" (solid, remove dead copper, pour order 214): 5061.5,750 5121.5,750 5121.5,665 5061.5,665
GND on Top Layer "TOP_LAYER_GND_P238" (solid, remove dead copper, pour order 238): 5231.5,835 5231.5,765 5171.5,765 5161.5,775 5161.5,825 5171.5,835
NetJ1.5_4 on Top Layer "TOP_LAYER_NETJ1.5_4_P157" (solid, remove dead copper, pour order 157): 5453.43,1772.2 5318.43,1772.2 5318.43,1987.2 5453.43,1987.2
L+5 on Top Layer "TOP_LAYER_L+5_P165" (solid, remove dead copper, pour order 165): 5508.43,1617.2 5508.43,1712.2 5453.43,1767.2 5308.43,1767.2 5308.43,1653.43 5245,1590 5245,1522.2 5328.43,1522.2 5328.43,1562.2 5383.43,1617.2
GND on Top Layer "TOP_LAYER_GND_P173" (solid, remove dead copper, pour order 173): 5313.43,1987.2 5143.43,1987.2 5143.43,1777.2 5313.43,1777.2
NetJ1.5_2 on Top Layer "TOP_LAYER_NETJ1.5_2_P197" (solid, remove dead copper, pour order 197): 5303.43,1762.2 5143.43,1762.2 5143.43,1577.2 5303.43,1577.2
NetU31.5_4 on Top Layer "TOP_LAYER_NETU31.5_4_P213" (solid, remove dead copper, pour order 213): 5568.43,1612.2 5508.43,1612.2 5508.43,1697.2 5568.43,1697.2
GND on Top Layer "TOP_LAYER_GND_P237" (solid, remove dead copper, pour order 237): 5398.43,1527.2 5398.43,1597.2 5458.43,1597.2 5468.43,1587.2 5468.43,1537.2 5458.43,1527.2
NetJ1.4_4 on Top Layer "TOP_LAYER_NETJ1.4_4_P156" (solid, remove dead copper, pour order 156): 6437.68,1772.2 6302.68,1772.2 6302.68,1987.2 6437.68,1987.2
L+4 on Top Layer "TOP_LAYER_L+4_P164" (solid, remove dead copper, pour order 164): 6492.68,1617.2 6492.68,1712.2 6437.68,1767.2 6292.68,1767.2 6292.68,1632.2 6277.68,1617.2 6252.68,1592.2 6252.68,1522.2 6312.68,1522.2 6312.68,1562.2 6367.68,1617.2
GND on Top Layer "TOP_LAYER_GND_P172" (solid, remove dead copper, pour order 172): 6297.68,1987.2 6127.68,1987.2 6127.68,1777.2 6297.68,1777.2
NetJ1.4_2 on Top Layer "TOP_LAYER_NETJ1.4_2_P196" (solid, remove dead copper, pour order 196): 6287.68,1762.2 6127.68,1762.2 6127.68,1577.2 6287.68,1577.2
NetU31.4_4 on Top Layer "TOP_LAYER_NETU31.4_4_P212" (solid, remove dead copper, pour order 212): 6552.68,1612.2 6492.68,1612.2 6492.68,1697.2 6552.68,1697.2
GND on Top Layer "TOP_LAYER_GND_P236" (solid, remove dead copper, pour order 236): 6382.68,1527.2 6382.68,1597.2 6442.68,1597.2 6452.68,1587.2 6452.68,1537.2 6442.68,1527.2
NetJ1.3_4 on Top Layer "TOP_LAYER_NETJ1.3_4_P155" (solid, remove dead copper, pour order 155): 6160.75,590 6295.75,590 6295.75,375 6160.75,375
GND on Top Layer "TOP_LAYER_GND_P171" (solid, remove dead copper, pour order 171): 6300.75,375 6470.75,375 6470.75,585 6300.75,585
NetJ1.3_2 on Top Layer "TOP_LAYER_NETJ1.3_2_P195" (solid, remove dead copper, pour order 195): 6310.75,600 6470.75,600 6470.75,785 6310.75,785
NetU31.3_4 on Top Layer "TOP_LAYER_NETU31.3_4_P211" (solid, remove dead copper, pour order 211): 6045.75,750 6105.75,750 6105.75,665 6045.75,665
GND on Top Layer "TOP_LAYER_GND_P235" (solid, remove dead copper, pour order 235): 6215.75,835 6215.75,765 6155.75,765 6145.75,775 6145.75,825 6155.75,835
NetJ1.2_4 on Top Layer "TOP_LAYER_NETJ1.2_4_P154" (solid, remove dead copper, pour order 154): 7421.93,1772.2 7286.93,1772.2 7286.93,1987.2 7421.93,1987.2
L+2 on Top Layer "TOP_LAYER_L+2_P162" (solid, remove dead copper, pour order 162): 7476.93,1617.2 7476.93,1712.2 7421.93,1767.2 7276.93,1767.2 7276.93,1632.2 7261.93,1617.2 7236.93,1592.2 7236.93,1522.2 7296.93,1522.2 7296.93,1562.2 7351.93,1617.2
GND on Top Layer "TOP_LAYER_GND_P170" (solid, remove dead copper, pour order 170): 7281.93,1987.2 7111.93,1987.2 7111.93,1777.2 7281.93,1777.2
NetJ1.2_2 on Top Layer "TOP_LAYER_NETJ1.2_2_P194" (solid, remove dead copper, pour order 194): 7271.93,1762.2 7111.93,1762.2 7111.93,1577.2 7271.93,1577.2
NetU31.2_4 on Top Layer "TOP_LAYER_NETU31.2_4_P210" (solid, remove dead copper, pour order 210): 7536.93,1612.2 7476.93,1612.2 7476.93,1697.2 7536.93,1697.2
GND on Top Layer "TOP_LAYER_GND_P234" (solid, remove dead copper, pour order 234): 7366.93,1527.2 7366.93,1597.2 7426.93,1597.2 7436.93,1587.2 7436.93,1537.2 7426.93,1527.2
GND on Top Layer "TOP_LAYER_GND_P233" (solid, remove dead copper, pour order 233): 7200,835 7200,765 7140,765 7130,775 7130,825 7140,835
NetU31.1_4 on Top Layer "TOP_LAYER_NETU31.1_4_P209" (solid, remove dead copper, pour order 209): 7030,750 7090,750 7090,665 7030,665
NetJ1.1_2 on Top Layer "TOP_LAYER_NETJ1.1_2_P193" (solid, remove dead copper, pour order 193): 7295,600 7455,600 7455,785 7295,785
GND on Top Layer "TOP_LAYER_GND_P169" (solid, remove dead copper, pour order 169): 7285,375 7455,375 7455,585 7285,585
L+1 on Top Layer "TOP_LAYER_L+1_P161" (solid, remove dead copper, pour order 161): 7090,745 7090,650 7145,595 7290,595 7290,730 7305,745 7330,770 7330,840 7270,840 7270,800 7215,745
NetJ1.1_4 on Top Layer "TOP_LAYER_NETJ1.1_4_P153" (solid, remove dead copper, pour order 153): 7145,590 7280,590 7280,375 7145,375
1V25 on Top Layer "TOP_LAYER_1V25_P152" (solid, remove dead copper, pour order 152): 1940,1130 1995,1130 1995,1090 1940,1090
3V3 on Top Layer "TOP_LAYER_3V3_P151" (solid, remove dead copper, pour order 151): 1975,1235 1930,1235 1930,1285 1975,1285
GND on Top Layer "TOP_LAYER_GND_P148" (solid, remove dead copper, pour order 148): 1750,1095 1800,1095 1820,1115 1820,1255 1830,1265 1830,1320 1805,1320 1750,1265
NetC113_1 on Top Layer "TOP_LAYER_NETC113_1_P146" (solid, remove dead copper, pour order 146): 1850,1295 1875,1295 1910,1260 1925,1260 1925,1235 1935,1225 1975,1225 1975,1200 1935,1200 1925,1190 1925,1180 1875,1180 1850,1205
NetC114_2 on Top Layer "TOP_LAYER_NETC114_2_P145" (solid, remove dead copper, pour order 145): 1935,1095 1820,1095 1820,1115 1870,1165 1980,1165 1980,1135 1935,1135
NetC129.2_1 on Top Layer "TOP_LAYER_NETC129.2_1_P100" (solid, remove dead copper, pour order 100): 980,350 980,495 1035,495 1065,525 1065,550 1015,550 1015,580 1095,580 1095,350
GND on Top Layer "TOP_LAYER_GND_P144" (solid, remove dead copper, pour order 144): 1355,860 1355,275 925,275 925,860
NetC132.2_1 on Top Layer "TOP_LAYER_NETC132.2_1_P142" (solid, remove dead copper, pour order 142): 19 vertices, not listed, extent 1210,625 1335,800
3V3 on Top Layer "TOP_LAYER_3V3_P138" (solid, remove dead copper, pour order 138): 2315,1490 2315,1540 2415,1540 2415,1490
NetC104_2 on Top Layer "TOP_LAYER_NETC104_2_P137" (solid, remove dead copper, pour order 137): 2135,1130 2450,1130 2450,1165 2490,1165 2490,1130 2490,1070 2160,1070 2135,1095
NetC108_1 on Top Layer "TOP_LAYER_NETC108_1_P136" (solid, remove dead copper, pour order 136): 2010,1490 2230,1490 2260,1490 2260,1445 2365,1445 2365,1483.12 2395,1483.12 2395,1445 2420,1445 2420,1390 2420,1365 2245,1365 2245,1390 2010,1390
NetC103_1 on Top Layer "TOP_LAYER_NETC103_1_P107" (solid, remove dead copper, pour order 107): 2190,1210 2130,1210 2130,1260 2120,1270 2010,1270 2009.76,1270.24 2009.76,1340.63 2230.24,1340.63 2230,1340.39 2230,1270 2200,1270 2190,1260
GND on Top Layer "TOP_LAYER_GND_P135" (solid, remove dead copper, pour order 135): 2075,1200 2075,1140 2210,1140 2255,1185 2440,1185 2440,1340 2240,1340 2240,1260 2200,1260 2200,1200
24V on Top Layer "TOP_LAYER_24V_P133" (solid, remove dead copper, pour order 133): 2600,1425 2600.82,1425.82 3150,1425.82 3150,1185 2600,1185
GND on Top Layer "TOP_LAYER_GND_P130" (solid, remove dead copper, pour order 130): 3460,1635 3740,1635 3740,1290 3345,1290 3345,1520
Vcore on Top Layer "TOP_LAYER_VCORE_P109" (solid, remove dead copper, pour order 109): 3160,470 3175,470 3190,455 3220,455 3225,450 3225,430 3215,420 3190,420 3170,400 3160,400 3155,405 3155,465
Vcore on Top Layer "TOP_LAYER_VCORE_P128" (solid, remove dead copper, pour order 128): 2905,650 2950,650 2950,417.76 2965,400 3140,400 3140,610 3185,610 3185,360 3000,360 3000,325 2970,325 2970,362.07 2905,424.08
L+4 on Bottom Layer "BOTTOM_LAYER_L+4_P319" (solid, remove dead copper, pour order 319): 6475,1320 6575,1320 6575,1220 6475,1220
L+6 on Bottom Layer "BOTTOM_LAYER_L+6_P318" (solid, remove dead copper, pour order 318): 5045,1140 5145,1140 5145,1040 5045,1040
L+7 on Bottom Layer "BOTTOM_LAYER_L+7_P317" (solid, remove dead copper, pour order 317): 4466.42,1762.2 4516.42,1712.2 4516.42,1622.2 4356.42,1622.2 4356.42,1742.2 4376.42,1762.2
L+5 on Bottom Layer "BOTTOM_LAYER_L+5_P316" (solid, remove dead copper, pour order 316): 5450.67,1762.2 5500.67,1712.2 5500.67,1622.2 5340.67,1622.2 5340.67,1742.2 5360.67,1762.2
L+2 on Bottom Layer "BOTTOM_LAYER_L+2_P315" (solid, remove dead copper, pour order 315): 7419.17,1762.2 7469.17,1712.2 7469.17,1622.2 7309.17,1622.2 7309.17,1742.2 7329.17,1762.2
L+1 on Bottom Layer "BOTTOM_LAYER_L+1_P314" (solid, remove dead copper, pour order 314): 7147.76,600 7097.76,650 7097.76,740 7257.76,740 7257.76,620 7237.76,600
L+3 on Bottom Layer "BOTTOM_LAYER_L+3_P313" (solid, remove dead copper, pour order 313): 6163.5,600 6113.5,650 6113.5,740 6273.5,740 6273.5,620 6253.5,600
L+6 on Bottom Layer "BOTTOM_LAYER_L+6_P312" (solid, remove dead copper, pour order 312): 5179.25,600 5129.25,650 5129.25,740 5289.25,740 5289.25,620 5269.25,600
L+8 on Bottom Layer "BOTTOM_LAYER_L+8_P311" (solid, remove dead copper, pour order 311): 4195,600 4145,650 4145,740 4305,740 4305,620 4285,600
EARTH on Bottom Layer "BOTTOM_LAYER_EARTH_P310" (solid, remove dead copper, pour order 310): 500,0 500,2365 0,2365 0,0
L+4 on Bottom Layer "BOTTOM_LAYER_L+4_P302" (solid, remove dead copper, pour order 302): 6315,1760 6445,1760 6495,1710 6495,1615 6550,1560 6550,1335 6470,1335 6470,1420 6315,1575
GND on Bottom Layer "BOTTOM_LAYER_GND_P300" (solid, remove dead copper, pour order 300): 6575,1010 6640,1010 6640,935 6575,935
L+3 on Bottom Layer "BOTTOM_LAYER_L+3_P297" (solid, remove dead copper, pour order 297): 6470,1145 6575,1145 6575,1030 6565,1020 6565,945 6470,945
NetQ4_1 on Bottom Layer "BOTTOM_LAYER_NETQ4_1_P294" (solid, remove dead copper, pour order 294): 6700,1210 6700,1245 6685,1245 6625,1305 6580,1305 6580,1220 6660,1220 6670,1210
